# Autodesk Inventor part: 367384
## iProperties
Created: 2006-08
Part Number: 367384
Material: A2
Description: Zylinderschraube
Vendor: Autodesk Inc.
Document SubType Name: Modeling
Standard: DIN 6912
Designer: I.Baliuc
Standards Organization: DIN
Language: de-DE
Size Designation: M8 x 16
Categories: <MemberInstance Version="R10.0.0"><Categories><Category DisplayName="Schrauben" InternalName="e4da775c-781d-43d5-af7c-5136215cf5a6" Mnemonic="FSTN"><Category Di
Density: 8.08 g/cm^3
Abmessung: M8 x 16
Author: T.Messerschmitt
Comments: DIN 6912 - M8 x 16
Revision Number: 367384
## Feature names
1. Körper [Revolution]
2. Loch [Extrusion]
3. Fase1 [Chamfer]
